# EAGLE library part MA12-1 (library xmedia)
PIN HEADER
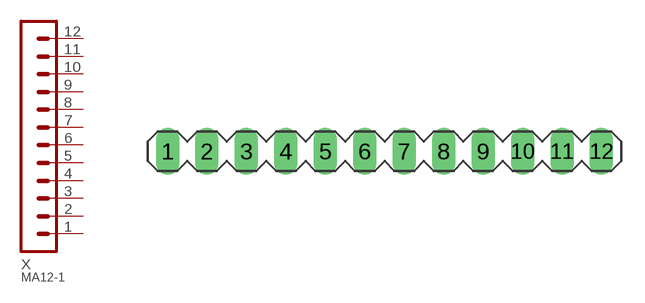
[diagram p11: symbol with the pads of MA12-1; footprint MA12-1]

Designator prefix X

## MA12-1  [MA12-1]
1  1  pas
2  2  pas
3  3  pas
4  4  pas
5  5  pas
6  6  pas
7  7  pas
8  8  pas
9  9  pas
10  10  pas
11  11  pas
12  12  pas

## Footprint MA12-1 (pad centres in mm)
PIN HEADER
drill 1.016 long: 1 -13.97,0; 2 -11.43,0; 3 -8.89,0; 4 -6.35,0; 5 -3.81,0; 6 -1.27,0; 7 1.27,0; 8 3.81,0; 9 6.35,0; 10 8.89,0; 11 11.43,0; 12 13.97,0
